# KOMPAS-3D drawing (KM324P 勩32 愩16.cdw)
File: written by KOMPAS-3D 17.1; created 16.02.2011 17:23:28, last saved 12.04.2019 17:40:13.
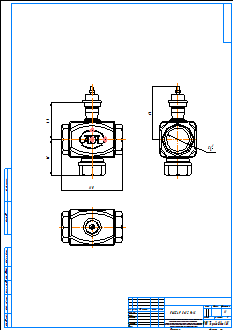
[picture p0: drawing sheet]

Title block, sheet 1: name: KM324P Ду32 Ру16; material: Внимание! Данный продукт является объектом авторского права ООО «Торговый Дом АДЛ». / Запрещается изменение, копирование, распространение / (в том числе путем копирования на другие сайты и ресурсы в Интернете) / или любое иное использование информации и объектов без предварительного / согласия правообладателя (ООО «Торговый Дом АДЛ»).; scale: 1:1; sheets: 1; organisation: ООО "Торговый дом АДЛ"; sheet format: A2; stored path: \\adlc.lan\data\АДЛ_ПКД\3D-модели\ADL production\Клапаны ГРАНРЕГ\Трёхходовой клапан KM324P\KOMPAS 2D\KM324P Ду32 Ру16.cdw

Views: Спереди 1, Проекционный вид 2, Проекционный вид 3
Dimensions and other numbers on the sheet: 110; 65; 67; 96; 1 1 4; 1:1; 1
